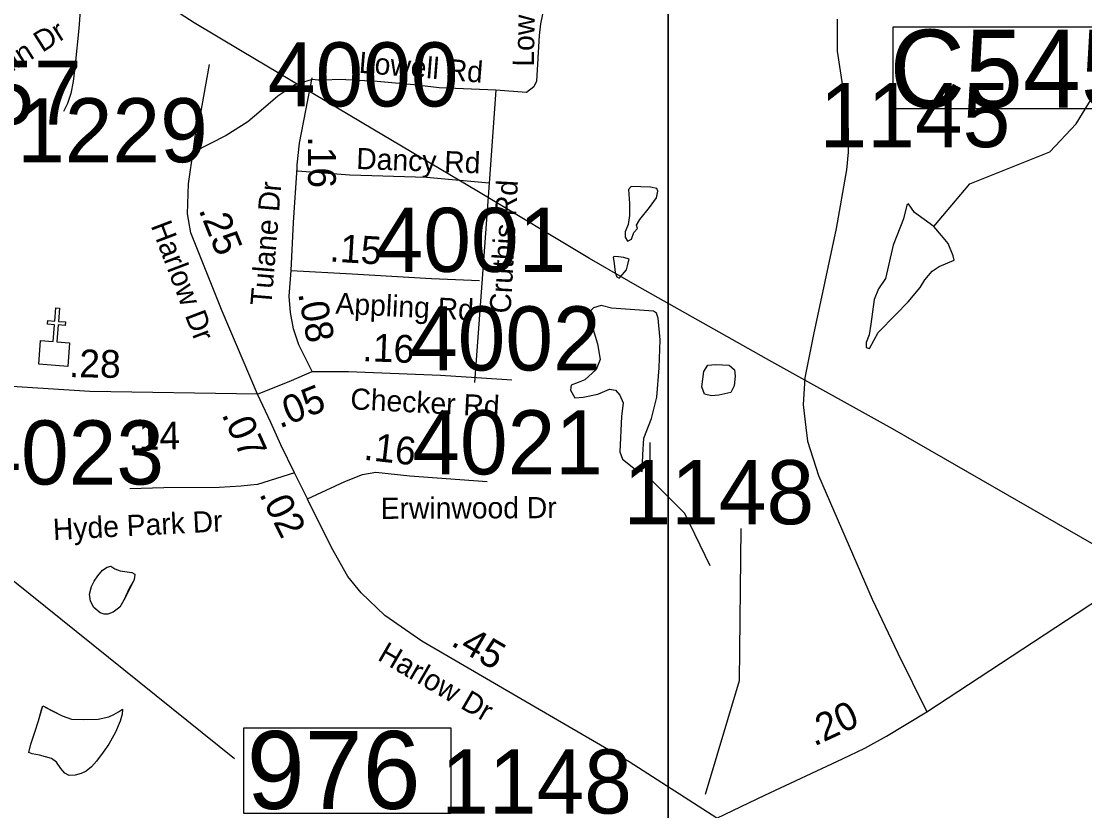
# Model space of a CAD drawing. Extents: x 1662474 to 1856135, y 779280 to 917889.
# Drawn here: x 1728129 to 1732908, y 791862 to 795409 of the extents above; entities that cross this region are included whole.
import ezdxf

# ---------------------------------------------------------------- set-up
doc = ezdxf.new("R2010")
doc.units = 0
for name, color, linetype in [('Cogo Default Point CELL', 7, 'Continuous'), ('Exist Cultural Church CELL', 7, 'Continuous'), ('Exist Hydrographic Misc Water Feature', 7, 'Continuous'), ('Exist Hydrographic Pond Under 1500 Sq Ft', 7, 'Continuous'), ('Exist Road Non-System Type 51', 7, 'Continuous'), ('Exist Road Non-System Type 51 Label', 7, 'Continuous'), ('Exist Road Primary Interstate Structure Culvert Number Label', 7, 'Continuous'), ('Exist Road Primary NC Attributed', 7, 'Continuous'), ('Exist Road Secondary Mileage Tenths English Label', 7, 'Continuous'), ('Exist Road Secondary Type 51 Attributed', 7, 'Continuous'), ('Exist Road Secondary Type 51 Label', 7, 'Continuous'), ('Exist Utilities Electrical Transmission Line', 7, 'Continuous'), ('Map Preparation Inset Cut Line', 7, 'Continuous'), ('Prop DGN Element Guardrail', 7, 'Continuous'), ('Prop Guardrail', 7, 'Continuous'), ('Scratch_Level_2', 7, 'Continuous')]:
    doc.layers.add(name, color=color, linetype=linetype)

msp = doc.modelspace()

# ---------------------------------------------------------------- linework, layer by layer
at = {"layer": 'Cogo Default Point CELL'}
msp.add_lwpolyline([(1731204.4, 791936), (1731357, 792446.9), (1731363.6, 793130.3)], dxfattribs=at)
at = {"layer": 'Exist Cultural Church CELL'}
msp.add_lwpolyline([(1728216.3, 793974.2), (1728273.1, 793970.1), (1728278.7, 794046), (1728246.8, 794048.4), (1728248, 794064.3), (1728279.9, 794062), (1728284.4, 794121.9), (1728300.4, 794120.7), (1728295.9, 794060.8), (1728327.8, 794058.4), (1728326.6, 794042.5), (1728294.7, 794044.8), (1728289, 793968.9), (1728346.5, 793964.5), (1728338.6, 793858.4), (1728208.4, 793868.1)], close=True, dxfattribs=at)
at = {"layer": 'Exist Hydrographic Misc Water Feature'}
for points in [[(1732230.4, 794486.6), (1732391.5, 794678.7), (1732751.6, 794822.4), (1732869.5, 794948), (1732954.6, 795087.4), (1733060.4, 795745), (1733196.6, 796093.4), (1733417.6, 796518.9), (1733594.6, 796682.7), (1733728.5, 796755.5), (1734037.5, 796828), (1734598.5, 797148), (1734846.9, 797367.9)], [(1728393.2, 795456.8), (1728388.5, 795376.8), (1728370.9, 795214.9), (1728362.3, 795139), (1728351.6, 795085), (1728337.3, 795039.3), (1728319, 795003.4)], [(1731225.4, 792962.8), (1731110.4, 793198.1), (1730953.5, 793355.6), (1730955.6, 793516.4)], [(1728531.6, 792960.8), (1728549.5, 792948.6), (1728573.5, 792940.4), (1728625.4, 792931.9), (1728639.3, 792925.7), (1728637, 792899.8), (1728614.7, 792859.9), (1728590.1, 792808.2), (1728571.8, 792776.3), (1728541.7, 792754.6), (1728517.5, 792744.8), (1728501.5, 792745), (1728483.7, 792751.1), (1728455.8, 792775.4), (1728440, 792803.6), (1728436.5, 792835.6), (1728444.7, 792869.6), (1728457, 792893.4), (1728473.2, 792917.3), (1728493.5, 792943.1), (1728515.7, 792956.9), (1728531.6, 792960.8)], [(1728531.6, 792960.8), (1728549.5, 792948.6), (1728573.5, 792940.4), (1728625.4, 792931.9), (1728639.3, 792925.7), (1728637, 792899.8), (1728590.1, 792808.2), (1728571.8, 792776.3), (1728541.7, 792754.6), (1728517.5, 792744.8), (1728501.5, 792745), (1728483.7, 792751.1), (1728455.8, 792775.4), (1728440, 792803.6), (1728436.5, 792835.6), (1728444.7, 792869.6), (1728457, 792893.4), (1728473.2, 792917.3), (1728493.5, 792943.1), (1728515.7, 792956.9), (1728531.6, 792960.8)], [(1728225.5, 792333.5), (1728265.5, 792313.1), (1728313.3, 792288.6), (1728355.1, 792274.2), (1728409, 792271.7), (1728475.3, 792273.1), (1728523.2, 792284.6), (1728545.4, 792294.4), (1728565.5, 792306.2), (1728583.5, 792318.1), (1728583.3, 792296), (1728573.1, 792264.2), (1728552.6, 792214.4), (1728522, 792160.6), (1728497.6, 792124.9), (1728467.3, 792085.1), (1728445.1, 792059.3), (1728420.9, 792039.6), (1728398.8, 792029.7), (1728370.7, 792022), (1728344.6, 792020.2), (1728324.8, 792030.4), (1728306.9, 792052.6), (1728287.2, 792080.8), (1728265.5, 792097), (1728211.6, 792111.5), (1728177.5, 792117.8), (1728163.6, 792124), (1728172, 792161.9), (1728190.6, 792215.8), (1728206.8, 792265.6), (1728219.4, 792315.5), (1728225.5, 792333.5)], [(1728225.5, 792333.5), (1728313.3, 792288.6), (1728355.1, 792274.2), (1728409, 792271.7), (1728475.3, 792273.1), (1728523.2, 792284.6), (1728545.4, 792294.4), (1728565.5, 792306.2), (1728583.5, 792318.1), (1728583.3, 792296), (1728573.1, 792264.2), (1728552.6, 792214.4), (1728522, 792160.6), (1728497.6, 792124.9), (1728467.3, 792085.1), (1728445.1, 792059.3), (1728420.9, 792039.6), (1728398.8, 792029.7), (1728370.7, 792022), (1728344.6, 792020.2), (1728324.8, 792030.4), (1728306.9, 792052.6), (1728287.2, 792080.8), (1728265.5, 792097), (1728211.6, 792111.5), (1728177.5, 792117.8), (1728163.6, 792124), (1728172, 792161.9), (1728190.6, 792215.8), (1728206.8, 792265.6), (1728225.5, 792333.5)]]:
    msp.add_lwpolyline(points, dxfattribs=at)
at = {"layer": 'Exist Hydrographic Pond Under 1500 Sq Ft'}
for points in [[(1730908.5, 794518.3), (1730952.4, 794572.8), (1730984.4, 794615.5), (1730989.8, 794645.4), (1730985.5, 794658.2), (1730956.6, 794664.6), (1730870.1, 794666.8), (1730858.3, 794654), (1730862.6, 794590.9), (1730862.6, 794536.5), (1730856.2, 794495.9), (1730843.3, 794463.8), (1730842.3, 794439.2), (1730853, 794421.1), (1730871.1, 794429.6), (1730881.8, 794460.6), (1730897.8, 794478.8), (1730893.6, 794493.7), (1730908.5, 794518.3)], [(1732230.4, 794486.6), (1732143.6, 794550.2), (1732116.6, 794588.7), (1732108.9, 794583), (1732093.5, 794521.3), (1732047.2, 794403.7), (1732012.5, 794253.4), (1731981.7, 794207.1), (1731962.4, 794158.9), (1731946.9, 794049), (1731939.2, 794000.9), (1731925.7, 793966.2), (1731925.7, 793943), (1731941.2, 793939.2), (1731979.7, 794010.5), (1732058.8, 794091.4), (1732114.7, 794149.3), (1732168.7, 794212.9), (1732189.9, 794247.6), (1732222.7, 794286.1), (1732253.6, 794307.3), (1732321.1, 794336.2), (1732317.2, 794355.5), (1732294.1, 794411.4), (1732265.1, 794446.1), (1732230.4, 794486.6)], [(1730836.9, 794347.4), (1730813.4, 794351.6), (1730795.2, 794352.7), (1730788.8, 794349.5), (1730793.1, 794320.7), (1730797.4, 794281.1), (1730804.9, 794260.8), (1730815.5, 794255.5), (1730820.9, 794259.8), (1730848.7, 794291.8), (1730853, 794311.1), (1730858.3, 794330.3), (1730860.4, 794341), (1730836.9, 794347.4)], [(1730969.5, 794106.9), (1730781.9, 794119.8), (1730735.2, 794132.1), (1730700.9, 794122.3), (1730688.6, 794110), (1730688.6, 794058.5), (1730718, 793960.3), (1730730.3, 793889.1), (1730713.1, 793844.9), (1730661.6, 793798.2), (1730632.1, 793786), (1730600.2, 793773.7), (1730597.7, 793751.6), (1730617.3, 793717.2), (1730654.2, 793719.7), (1730720.5, 793734.4), (1730772.1, 793756.5), (1730799.1, 793751.6), (1730818.7, 793729.5), (1730833.5, 793695.1), (1730826.1, 793633.8), (1730818.7, 793474.2), (1730831, 793442.3), (1730890, 793395.6), (1730919.4, 793385.8), (1730921.9, 793461.9), (1730926.8, 793535.6), (1730961.2, 793623.9), (1730985.8, 793719.7), (1730995.6, 793852.2), (1731000.5, 793977.4), (1730990.7, 794075.6), (1730983.3, 794097.7), (1730969.5, 794106.9)], [(1731199.4, 793734.4), (1731187.2, 793766.3), (1731197, 793835.1), (1731214.2, 793864.5), (1731251, 793867), (1731310, 793864.5), (1731334.5, 793842.4), (1731337, 793815.4), (1731332.1, 793771.2), (1731317.3, 793741.8), (1731263.3, 793729.5), (1731231.4, 793727), (1731199.4, 793734.4)]]:
    msp.add_lwpolyline(points, dxfattribs=at)
at = {"layer": 'Exist Road Non-System Type 51'}
for p, q in [((1728973.6, 795215.2), (1728903.4, 794821.1)), ((1730261.9, 795099), (1730231.1, 794681.4)), ((1730231.1, 794681.4), (1730198.4, 794232.6)), ((1730198.4, 794232.6), (1730166.1, 793785.9))]:
    msp.add_line(p, q, dxfattribs=at)
for points in [[(1730471.6, 795516.6), (1730480.2, 795484), (1730462.1, 795397.2), (1730456.4, 795345.2), (1730444.2, 795140.5), (1730432.8, 795114.5), (1730399.4, 795089.6), (1730261.9, 795099)], [(1729436.1, 795147.2), (1729358.8, 795124.4), (1729281.6, 795072.5), (1729207.9, 795007.9), (1729146.9, 794956.8), (1729050.4, 794895.4), (1728903.4, 794821.1)], [(1730261.9, 795099), (1730007.8, 795109.5), (1729893.1, 795123.7), (1729728.5, 795139.2), (1729559.8, 795147.2), (1729491.8, 795145.4), (1729462.9, 795145.4), (1729436.1, 795147.2)], [(1730231.1, 794681.4), (1729950.4, 794706.6), (1729605.6, 794717.7), (1729370.2, 794736)]]:
    msp.add_lwpolyline(points, dxfattribs=at)
at = {"layer": 'Exist Road Primary Interstate Structure Culvert Number Label'}
msp.add_lwpolyline([(1732047.5, 795384.3), (1733345.4, 795384.3), (1733345.4, 795015.6), (1732047.5, 795015.6)], close=True, dxfattribs=at)
at = {"layer": 'Exist Road Primary NC Attributed'}
for points in [[(1732197.8, 792306.7), (1732433.9, 792461.1), (1732873.8, 792749.7), (1733229.5, 792983.7), (1733336.6, 793048.7), (1733420.8, 793100.7), (1733514.4, 793149.6), (1733631.9, 793212), (1733805.6, 793289.9), (1734047.9, 793371.6), (1734433.7, 793505.2), (1734764.4, 793625.3), (1734988, 793698.6), (1735113.9, 793737.1)], [(1731254.6, 791829.3), (1731470.9, 791931.8), (1731820.3, 792095), (1731920.2, 792143.4), (1732017.9, 792197.5), (1732197.8, 792306.7)]]:
    msp.add_lwpolyline(points, dxfattribs=at)
at = {"layer": 'Exist Road Secondary Type 51 Attributed'}
for points in [[(1731796.3, 795419), (1731796.3, 795275.7), (1731842.8, 794960), (1731844.7, 794899.9), (1731844.7, 794820.5), (1731837, 794741.1), (1731791.4, 794477.6), (1731688.9, 794001.4), (1731650.9, 793807.9), (1731643.3, 793686.4), (1731654.7, 793584), (1731662.3, 793523.3), (1731711.7, 793367.7), (1731952.4, 792813.1), (1732068.9, 792570.8), (1732197.8, 792306.7)], [(1729341.5, 794288.9), (1729352.4, 794504.6), (1729368.8, 794750.4), (1729368.8, 794764), (1729379.7, 794862.3), (1729437.1, 795154.5)], [(1729190.1, 793733.2), (1729032.6, 794107.1), (1728891.7, 794458.3), (1728876.1, 794543.7), (1728880, 794679.6), (1728903.3, 794835), (1728924.2, 794991.8)], [(1729437.1, 793835.6), (1729377, 793955.7), (1729352.4, 794026.7), (1729338.7, 794100.4), (1729333.3, 794174.2), (1729341.5, 794288.9)], [(1729341.5, 794288.9), (1729615.7, 794274.6), (1729972.9, 794252.8), (1730188.3, 794244.6)], [(1729190.1, 793733.2), (1729344.2, 793794.6), (1729437.1, 793835.6)], [(1729437.1, 793835.6), (1729599.4, 793835.9), (1730013.8, 793819.5), (1730174.7, 793808.6), (1730332.9, 793797.7)], [(1729190.1, 793733.2), (1728437.6, 793746.5), (1727735.5, 793790.7)], [(1729356.3, 793380.2), (1729295.7, 793505.7), (1729250.4, 793606.1), (1729190.1, 793733.2)], [(1729356.3, 793380.2), (1729190.1, 793327.3), (1729159.9, 793324.8), (1729117.2, 793319.8), (1729019.2, 793314.7), (1728769.3, 793313), (1728617.2, 793308.5)], [(1729415.2, 793263.4), (1729356.3, 793380.2)], [(1729415.2, 793263.4), (1729583.4, 793342), (1729663.3, 793373.3), (1729722.4, 793383.7), (1729875.2, 793366.3), (1730222.5, 793342)], [(1731254.6, 791829.3), (1730861.5, 792081.3), (1730373.8, 792364.9), (1729929.7, 792623.8), (1729763.2, 792739.4), (1729656.8, 792841.1), (1729596.6, 792915.1), (1729522.6, 793044.5), (1729416.1, 793261.4), (1729415.2, 793263.4)]]:
    msp.add_lwpolyline(points, dxfattribs=at)
at = {"layer": 'Exist Utilities Electrical Transmission Line'}
msp.add_lwpolyline([(1732950.7, 793057.3), (1732044.2, 793577.3), (1731502.5, 793878.4), (1730909.3, 794212.5), (1730683.2, 794343.5), (1730183.4, 794642.2), (1729709.6, 794924.6), (1729122.3, 795274.2), (1728906.3, 795403), (1728541.9, 795637.9), (1727850.4, 796112.8), (1727349.4, 796463.7), (1727121.4, 796612.4), (1726679.7, 796922.4), (1726097.4, 797328.1), (1725657.9, 797632.2), (1725283.6, 797886.9), (1724723.3, 798268.3), (1724192.5, 798635.2), (1723828, 798890.1), (1723315.1, 799251.1)], dxfattribs=at)
at = {"layer": 'Map Preparation Inset Cut Line'}
for points in [[(1731035.7, 782767.4), (1668486.3, 782767.4), (1668486.3, 826588.1), (1731035.7, 826588.1)], [(1793585.1, 782767.4), (1731035.7, 782767.4), (1731035.7, 826588.1), (1793585.1, 826588.1)]]:
    msp.add_lwpolyline(points, close=True, dxfattribs=at)
at = {"layer": 'Scratch_Level_2'}
msp.add_line((1726505.7, 794167.7), (1729087, 792096.7), dxfattribs=at)
msp.add_lwpolyline([(1729130, 792234.5), (1730059, 792234.5), (1730059, 791850.4), (1729130, 791850.4)], close=True, dxfattribs=at)

# ---------------------------------------------------------------- texts
at = {"layer": 'Cogo Default Point CELL'}
for s, p in [('4000', (1729237.3, 795026.5)), ('1157', (1727543.9, 794945)), ('1145', (1731716.7, 794843.6)), ('1229', (1728110.6, 794775.7)), ('4001', (1729721.5, 794283.2)), ('4002', (1729876.2, 793840.3)), ('4021', (1729886.4, 793373.4)), ('4023', (1727913.9, 793327.9)), ('1148', (1730835.2, 793149.3)), ('1148', (1730016.4, 791849.4))]:
    msp.add_text(s, height=288, dxfattribs=at).set_placement(p)
at = {"layer": 'Exist Road Non-System Type 51 Label'}
for s, rotation, p in [('Lowell Rd', 88.9657, (1730432.5, 795204.7)), ('Joplin Dr', 32.3799, (1727913.7, 795070.3)), ('Lowell Rd', 355.3456, (1729644, 795178.2)), ('Dancy Rd', 357.9401, (1729633.5, 794745.9)), ('Cruthis Rd', 86.822, (1730328, 794094.6))]:
    msp.add_text(s, height=95, rotation=rotation, dxfattribs=at).set_placement(p)
at = {"layer": 'Exist Road Primary Interstate Structure Culvert Number Label'}
msp.add_text('C545', height=350, dxfattribs=at).set_placement((1732031.4, 795021.7))
at = {"layer": 'Exist Road Secondary Mileage Tenths English Label'}
for s, rotation, p in [('.16', 270, (1729418, 794892.4)), ('.25', 291.8665, (1728925.1, 794562.1)), ('.15', 356.5077, (1729512.5, 794330.2)), ('.08', 280.4985, (1729372.9, 794186.2)), ('.16', 357.741, (1729660.6, 793882.7)), ('.05', 21.7183, (1729290.7, 793579.1)), ('.16', 353.5215, (1729664.7, 793439.7)), ('.45', 329.7607, (1730055.1, 792607.7))]:
    msp.add_text(s, height=125, rotation=rotation, dxfattribs=at).set_placement(p)
at = {"layer": 'Exist Road Secondary Type 51 Label'}
for s, rotation, p in [('Tulane Dr', 85.3358, (1729253, 794128.6)), ('Harlow Dr', 290.8327, (1728710.1, 794491)), ('Appling Rd', 357.1864, (1729539.8, 794095.7)), ('Checker Rd', 357.0389, (1729606.3, 793666.1)), ('Erwinwood Dr', 0.2607, (1729744.6, 793173.4)), ('Hyde Park Dr', 2.9616, (1728274, 793078.3)), ('Harlow Dr', 329.8191, (1729725.5, 792542.5))]:
    msp.add_text(s, height=95, rotation=rotation, dxfattribs=at).set_placement(p)
at = {"layer": 'Prop DGN Element Guardrail'}
for s, rotation, p in [('.28', 358.9908, (1728342.6, 793810.6)), ('.07', 294.2419, (1729028.2, 793643)), ('.14', 0.3947, (1728611.4, 793484.1)), ('.02', 296.7912, (1729196.6, 793285.1))]:
    msp.add_text(s, height=125, rotation=rotation, dxfattribs=at).set_placement(p)
at = {"layer": 'Prop Guardrail'}
msp.add_text('.20', height=125, rotation=25.0449, dxfattribs=at).set_placement((1731692.4, 792149.9))
at = {"layer": 'Scratch_Level_2'}
msp.add_text('976', height=350, dxfattribs=at).set_placement((1729142.6, 791870.2))

doc.saveas('drawing.dxf')
